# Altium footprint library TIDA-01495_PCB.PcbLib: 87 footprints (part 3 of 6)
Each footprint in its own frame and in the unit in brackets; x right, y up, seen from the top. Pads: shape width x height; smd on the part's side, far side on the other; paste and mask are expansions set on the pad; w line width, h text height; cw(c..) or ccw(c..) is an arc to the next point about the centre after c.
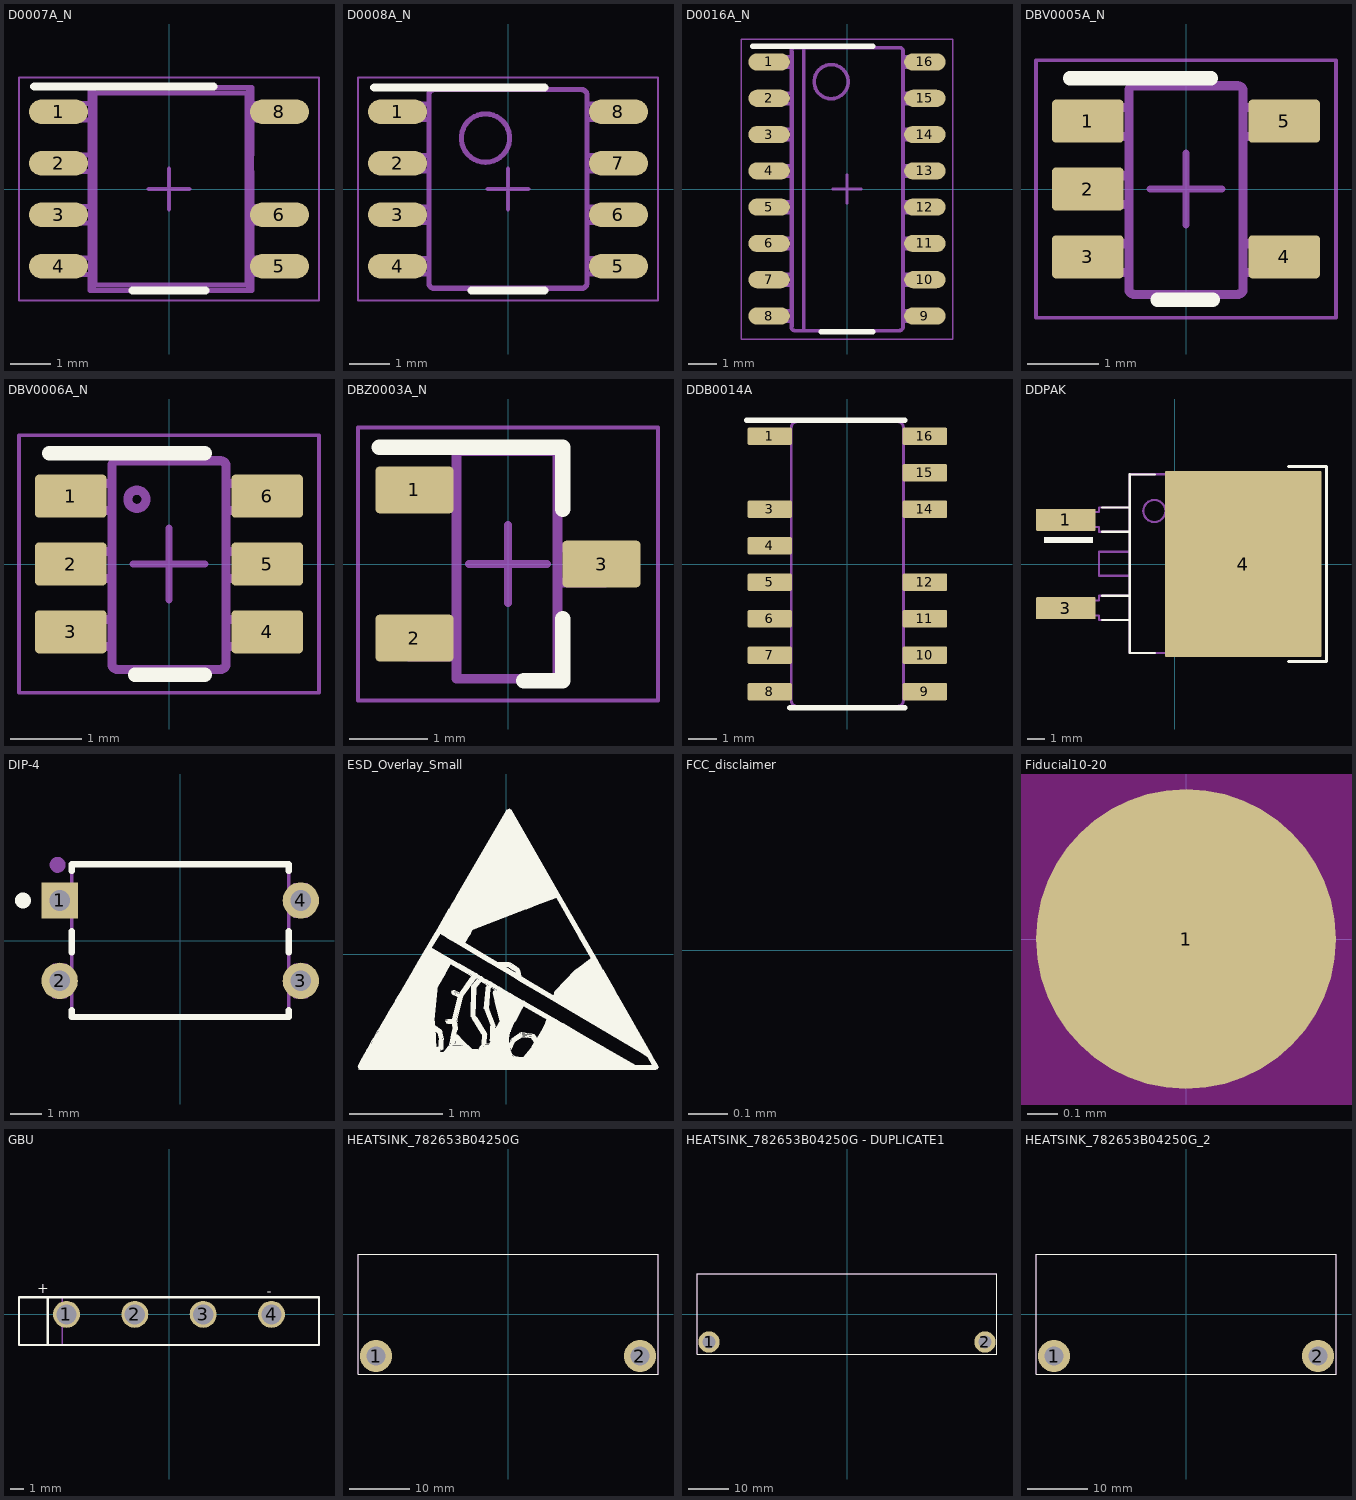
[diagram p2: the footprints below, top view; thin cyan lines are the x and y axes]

## D0007A_N [mm] "SOIC, 7-Leads, Body 4.9x3.9mm, Pitch 1.27mm, IPC Medium Density"
height 1.75
pads (7):
  oval 1.45x0.6 smd: 1(-2.725,1.905) 2(-2.725,0.635) 3(-2.725,-0.635) 4(-2.725,-1.905) 5(2.725,-1.905) 6(2.725,-0.635) 8(2.725,1.905)
Top Overlay:
  lines w0.2: -3.325,2.525 1.1,2.525 ; -0.9,-2.5 0.9,-2.5
Mechanical 5:
  lines w0.127: -1.95,-2.11 -1.95,-2.5 ; -1.95,-1.7 -1.95,-0.84 ; -1.95,-0.43 -1.95,0.43 ; -1.95,0.84 -1.95,1.7 ; -1.95,2.11 -1.95,2.5 ; 2.05,-2.11 2.05,-2.5 ; 2.05,-1.7 2.05,-0.84 ; 2.05,-0.43 2.05,0.43 2.03,0.43 2.03,0.84 2.05,0.84 2.05,1.7 ; 2.05,2.11 2.05,2.5 ; -2.325,-2.11 -2.325,-1.7 ; -2.325,-2.11 -2.045,-2.11 -1.931,-2.11 -1.931,-1.7 -2.045,-1.7 -2.325,-1.7 ; -2.325,-2.11 -2.39,-2.11 -2.95,-2.11 -2.95,-1.7 -2.39,-1.7 -2.325,-1.7 ; -2.325,-0.84 -2.325,-0.43 ; -2.325,-0.84 -2.045,-0.84 -1.931,-0.84 -1.931,-0.43 -2.045,-0.43 -2.325,-0.43 ; -2.325,-0.84 -2.39,-0.84 -2.95,-0.84 -2.95,-0.43 -2.39,-0.43 -2.325,-0.43 ; -2.325,0.43 -2.045,0.43 -1.931,0.43 -1.931,0.84 -2.045,0.84 -2.325,0.84 ; -2.325,0.43 -2.39,0.43 -2.95,0.43 -2.95,0.84 -2.39,0.84 -2.325,0.84 ; -2.325,0.43 -2.325,0.84 ; -2.325,1.7 -2.045,1.7 -1.931,1.7 -1.931,2.11 -2.045,2.11 -2.325,2.11 ; -2.325,1.7 -2.325,2.11 ; -2.325,1.7 -2.39,1.7 -2.95,1.7 -2.95,2.11 -2.39,2.11 -2.325,2.11 ; -1.95,-2.5 2.05,-2.5 ; -1.95,-2.5 -1.822,-2.372 ; -1.95,2.5 -1.822,2.372 ; -1.95,2.5 2.05,2.5 ; -1.822,-2.372 -1.822,2.372 ; -1.822,-2.372 1.922,-2.372 ; -1.822,2.372 1.922,2.372 ; 1.922,-2.372 1.922,2.372 ; 1.922,-2.372 2.05,-2.5 ; 1.922,2.372 2.05,2.5 ; 2.425,-2.11 2.49,-2.11 3.05,-2.11 3.05,-1.7 2.49,-1.7 2.425,-1.7 ; 2.425,-2.11 2.145,-2.11 2.031,-2.11 2.031,-1.7 2.145,-1.7 2.425,-1.7 ; 2.425,-2.11 2.425,-1.7 ; 2.425,-0.84 2.49,-0.84 3.05,-0.84 3.05,-0.43 2.49,-0.43 2.425,-0.43 ; 2.425,-0.84 2.145,-0.84 2.031,-0.84 2.031,-0.43 2.145,-0.43 2.425,-0.43 ; 2.425,-0.84 2.425,-0.43 ; 2.425,1.7 2.49,1.7 3.05,1.7 3.05,2.11 2.49,2.11 2.425,2.11 ; 2.425,1.7 2.145,1.7 2.031,1.7 2.031,2.11 2.145,2.11 2.425,2.11 ; 2.425,1.7 2.425,2.11
  text ".Designator" at -1.4,-0.4 h0.76
Mechanical 15:
  lines w0.05: -3.7,-2.75 3.7,-2.75 3.7,2.75 -3.7,2.75 -3.7,-2.75
  lines w0.1: -0.5,0 0.5,0 ; 0,-0.5 0,0.5
3D body "D0007A.stp": height 1.75, standoff 0, extent -3.01,-2.45 3.01,2.45

## D0008A_N [mm] "SOIC, 8-Leads, Body 4.9x3.9mm, Pitch 1.27mm, IPC Medium Density"
height 1.75
pads (8):
  oval 1.45x0.6 smd: 1(-2.725,1.905) 2(-2.725,0.635) 3(-2.725,-0.635) 4(-2.725,-1.905) 5(2.725,-1.905) 6(2.725,-0.635) 7(2.725,0.635) 8(2.725,1.905)
Top Overlay:
  lines w0.2: -3.3,2.5 0.9,2.5 ; -0.9,-2.5 0.9,-2.5
Mechanical 5:
  lines w0.127: -2.375,-2.095 -2.375,-1.715 ; -2.375,-2.095 -2.589,-2.095 -3.002,-2.095 -3.002,-1.715 -2.589,-1.715 -2.375,-1.715 ; -2.375,-2.095 -1.995,-2.095 -1.952,-2.095 -1.952,-1.715 -1.995,-1.715 -2.375,-1.715 ; -2.375,-0.825 -2.375,-0.445 ; -2.375,-0.825 -2.589,-0.825 -3.002,-0.825 -3.002,-0.445 -2.589,-0.445 -2.375,-0.445 ; -2.375,-0.825 -1.995,-0.825 -1.952,-0.825 -1.952,-0.445 -1.995,-0.445 -2.375,-0.445 ; -2.375,0.445 -2.375,0.825 ; -2.375,0.445 -2.589,0.445 -3.002,0.445 -3.002,0.825 -2.589,0.825 -2.375,0.825 ; -2.375,0.445 -1.995,0.445 -1.952,0.445 -1.952,0.825 -1.995,0.825 -2.375,0.825 ; -2.375,1.715 -2.375,2.095 ; -2.375,1.715 -2.589,1.715 -3.002,1.715 -3.002,2.095 -2.589,2.095 -2.375,2.095 ; -2.375,1.715 -1.995,1.715 -1.952,1.715 -1.952,2.095 -1.995,2.095 -2.375,2.095 ; -0.332,-2.45 -0.182,-2.45 ; -0.332,-2.45 -0.182,-2.45 ; -0.332,-2.45 -1.825,-2.45 -1.826,-2.45 cw(c-1.825,-2.323) -1.952,-2.324 -1.952,-2.323 -1.952,2.323 -1.952,2.324 cw(c-1.825,2.323) -1.826,2.45 -1.825,2.45 -0.332,2.45 ; -0.332,2.45 -0.182,2.45 ; -0.332,2.45 -0.182,2.45 ; -0.182,-2.45 0.178,-2.45 ; -0.182,2.45 0.178,2.45 ; 0.178,-2.45 0.328,-2.45 ; 0.178,-2.45 0.328,-2.45 ; 0.178,2.45 0.328,2.45 ; 0.178,2.45 0.328,2.45 ; 0.328,-2.45 1.821,-2.45 1.822,-2.45 ccw(c1.821,-2.323) 1.948,-2.324 1.948,-2.323 1.948,2.323 1.948,2.324 ccw(c1.821,2.323) 1.822,2.45 1.821,2.45 0.328,2.45 ; 2.371,-2.095 2.371,-1.715 ; 2.371,-2.095 1.991,-2.095 1.948,-2.095 1.948,-1.715 1.991,-1.715 2.371,-1.715 ; 2.371,-2.095 2.585,-2.095 2.998,-2.095 2.998,-1.715 2.585,-1.715 2.371,-1.715 ; 2.371,-0.825 2.371,-0.445 ; 2.371,-0.825 1.991,-0.825 1.948,-0.825 1.948,-0.445 1.991,-0.445 2.371,-0.445 ; 2.371,-0.825 2.585,-0.825 2.998,-0.825 2.998,-0.445 2.585,-0.445 2.371,-0.445 ; 2.371,0.445 2.371,0.825 ; 2.371,0.445 1.991,0.445 1.948,0.445 1.948,0.825 1.991,0.825 2.371,0.825 ; 2.371,0.445 2.585,0.445 2.998,0.445 2.998,0.825 2.585,0.825 2.371,0.825 ; 2.371,1.715 2.371,2.095 ; 2.371,1.715 1.991,1.715 1.948,1.715 1.948,2.095 1.991,2.095 2.371,2.095 ; 2.371,1.715 2.585,1.715 2.998,1.715 2.998,2.095 2.585,2.095 2.371,2.095 ; -0.555,0.659 ccw(c-0.555,1.256) -0.555,1.853 ccw(c-0.555,1.256) -0.555,0.659
  text ".Designator" at 0.411,-1.12 h0.89
Mechanical 15:
  lines w0.05: -3.7,-2.75 -3.7,2.75 3.7,2.75 3.7,-2.75 -3.7,-2.75
  lines w0.1: -0.5,0 0.5,0 ; 0,-0.5 0,0.5
3D body "D0008A.stp": height 1.63, standoff 0, extent -3,-2.45 3,2.45

## D0016A_N [mm] "SOIC, 16-Leads, Body 9.9x3.9mm, Pitch 1.27mm, IPC Medium Density"
height 1.75
pads (16):
  oval 1.45x0.6 smd: 1(-2.725,4.445) 2(-2.725,3.175) 3(-2.725,1.905) 4(-2.725,0.635) 5(-2.725,-0.635) 6(-2.725,-1.905) 7(-2.725,-3.175) 8(-2.725,-4.445) 9(2.725,-4.445) 10(2.725,-3.175) 11(2.725,-1.905) 12(2.725,-0.635) 13(2.725,0.635) 14(2.725,1.905) 15(2.725,3.175) 16(2.725,4.445)
Top Overlay:
  lines w0.2: -3.3,5 0.9,5 ; -0.9,-5 0.9,-5
Mechanical 5:
  drawing of 204 lines, arcs and shapes, not listed
  text ".Designator" at -1.2,-0.4 h0.76
Mechanical 15:
  lines w0.05: -3.7,-5.25 3.7,-5.25 3.7,5.25 -3.7,5.25 -3.7,-5.25
  lines w0.1: -0.5,0 0.5,0 ; 0,-0.5 0,0.5
3D body "D0016A.stp": height 1.6, standoff 0, extent -2.997,-4.953 2.997,4.953

## DBV0005A_N [mm] "SOT23, 5-Leads, Body 2.9x1.6mm, Pitch 0.95mm, Lead Span 2.8mm, IPC Medium Density"
height 1.45
pads (5):
  rrect17% 1x0.6 smd: 1(-1.375,0.95) 2(-1.375,0) 3(-1.375,-0.95) 4(1.375,-0.95) 5(1.375,0.95)
Top Overlay:
  lines w0.2: -1.625,1.55 0.35,1.55 ; -0.4,-1.55 0.375,-1.55
Mechanical 5:
  lines w0.127: -0.801,1.371 cw(c-0.725,1.37) -0.725,1.446 ; -0.801,1.37 -0.801,1.371 ; -0.801,1.37 -0.801,-1.399 -0.801,-1.4 ccw(c-0.725,-1.399) -0.725,-1.475 ; -0.725,-1.475 0.723,-1.475 0.724,-1.475 ccw(c0.723,-1.399) 0.799,-1.4 0.799,-1.399 0.799,1.37 ; -0.725,-1.475 -0.725,-1.475 ; -0.725,1.446 -0.725,1.446 ; -0.725,1.446 0.723,1.446 0.724,1.446 cw(c0.723,1.37) 0.799,1.371 ; 0.799,1.37 0.799,1.371 ; -1.423,-1.167 -1.423,-0.767 -1.199,-0.767 -1.105,-0.767 -1.088,-0.767 -0.835,-0.767 -0.801,-0.767 -0.801,-1.167 -0.835,-1.167 -1.088,-1.167 -1.105,-1.167 -1.199,-1.167 -1.423,-1.167 ; -1.423,-0.215 -1.423,0.186 -1.199,0.186 -1.105,0.186 -1.088,0.186 -0.835,0.186 -0.801,0.186 -0.801,-0.215 -0.835,-0.215 -1.088,-0.215 -1.105,-0.215 -1.199,-0.215 -1.423,-0.215 ; -1.423,0.738 -1.423,1.138 -1.199,1.138 -1.105,1.138 -1.088,1.138 -0.835,1.138 -0.801,1.138 -0.801,0.738 -0.835,0.738 -1.088,0.738 -1.105,0.738 -1.199,0.738 -1.423,0.738 ; 0.799,-1.167 0.834,-1.167 1.087,-1.167 1.103,-1.167 1.198,-1.167 1.422,-1.167 1.422,-0.767 1.198,-0.767 1.103,-0.767 1.087,-0.767 0.834,-0.767 0.799,-0.767 0.799,-1.167 ; 0.799,0.738 0.834,0.738 1.087,0.738 1.103,0.738 1.198,0.738 1.422,0.738 1.422,1.138 1.198,1.138 1.103,1.138 1.087,1.138 0.834,1.138 0.799,1.138 0.799,0.738
  text ".Designator" at 0.263,-0.693 h0.51
Mechanical 15:
  lines w0.05: -2.1,-1.8 -2.1,1.8 2.1,1.8 2.1,-1.8 -2.1,-1.8
  lines w0.1: -0.5,0 0.5,0 ; 0,-0.5 0,0.5
3D body "DBV0005A.stp": height 1.09, standoff 0, extent -1.422,-1.46 1.422,1.461

## DBV0006A_N [mm] "SOT23, 6-Leads, Body 2.9x1.6mm, Pitch 0.95mm, Lead Span 2.8mm, IPC Medium Density"
height 1.45
pads (6):
  rrect17% 1x0.6 smd: 1(-1.375,0.95) 2(-1.375,0) 3(-1.375,-0.95) 4(1.375,-0.95) 5(1.375,0) 6(1.375,0.95)
Top Overlay:
  lines w0.2: -1.675,1.55 0.5,1.55 ; -0.475,-1.55 0.5,-1.55
Mechanical 5:
  lines w0.127: 0.724,-1.475 ccw(c0.723,-1.399) 0.8,-1.399 0.8,1.37 ccw(c0.723,1.37) 0.724,1.446 ; 0.723,-1.475 0.724,-1.475 ; 0.723,-1.475 -0.724,-1.475 -0.725,-1.475 cw(c-0.724,-1.399) -0.801,-1.399 -0.801,1.37 cw(c-0.724,1.37) -0.725,1.446 -0.724,1.446 0.723,1.446 ; 0.723,1.446 0.724,1.446 ; -1.423,-1.154 -1.206,-1.154 -1.113,-1.154 -1.081,-1.154 -0.828,-1.154 -0.801,-1.154 -0.801,-0.78 -0.828,-0.78 -1.081,-0.78 -1.113,-0.78 -1.206,-0.78 -1.423,-0.78 -1.423,-1.154 ; -1.423,-0.202 -1.206,-0.202 -1.113,-0.202 -1.081,-0.202 -0.828,-0.202 -0.801,-0.202 -0.801,0.173 -0.828,0.173 -1.081,0.173 -1.113,0.173 -1.206,0.173 -1.423,0.173 -1.423,-0.202 ; -1.423,0.751 -1.206,0.751 -1.113,0.751 -1.081,0.751 -0.828,0.751 -0.801,0.751 -0.801,1.125 -0.828,1.125 -1.081,1.125 -1.113,1.125 -1.206,1.125 -1.423,1.125 -1.423,0.751 ; -0.577,0.906 cw(c-0.45,0.906) -0.323,0.906 cw(c-0.45,0.906) -0.577,0.906 ; 0.8,-1.154 0.827,-1.154 1.08,-1.154 1.112,-1.154 1.205,-1.154 1.422,-1.154 1.422,-0.78 1.205,-0.78 1.112,-0.78 1.08,-0.78 0.827,-0.78 0.8,-0.78 0.8,-1.154 ; 0.8,-0.202 0.827,-0.202 1.08,-0.202 1.112,-0.202 1.205,-0.202 1.422,-0.202 1.422,0.173 1.205,0.173 1.112,0.173 1.08,0.173 0.827,0.173 0.8,0.173 0.8,-0.202 ; 0.8,0.751 0.827,0.751 1.08,0.751 1.112,0.751 1.205,0.751 1.422,0.751 1.422,1.125 1.205,1.125 1.112,1.125 1.08,1.125 0.827,1.125 0.8,1.125 0.8,0.751
  text ".Designator" at -0.075,0.925 h0.51
Mechanical 15:
  lines w0.05: -2.1,-1.8 2.1,-1.8 2.1,1.8 -2.1,1.8 -2.1,-1.8
  lines w0.1: -0.5,0 0.5,0 ; 0,-0.5 0,0.5
3D body "DBV0006A.stp": height 1.12, standoff 0, extent -1.422,-1.461 1.423,1.46

## DBZ0003A_N [mm] "SOT23, 3-Leads, Body 2.9x1.3mm, Pitch 0.95mm, Lead Span 2.4mm, IPC Medium Density"
height 1.12
pads (3):
  rrect17% 1x0.6 smd: 1(-1.2,0.95) 2(-1.2,-0.95) 3(1.2,0)
Top Overlay:
  lines w0.2: -1.651,1.5 0.7,1.5 0.7,0.7 ; 0.2,-1.5 0.7,-1.5 0.7,-0.7
Mechanical 5:
  lines w0.127: -1.27,-1.187 -1.27,-0.743 -1.063,-0.743 -1.005,-0.743 -0.814,-0.743 -0.66,-0.743 -0.66,-1.187 -0.814,-1.187 -1.005,-1.187 -1.063,-1.187 -1.27,-1.187 ; -1.27,0.718 -1.27,1.162 -1.063,1.162 -1.005,1.162 -0.814,1.162 -0.66,1.162 -0.66,0.718 -0.814,0.718 -1.005,0.718 -1.063,0.718 -1.27,0.718 ; -0.66,-1.473 -0.66,1.448 0.635,1.448 0.635,-1.473 -0.66,-1.473 ; 0.635,-0.235 0.789,-0.235 0.98,-0.235 1.037,-0.235 1.245,-0.235 1.245,0.21 1.037,0.21 0.98,0.21 0.789,0.21 0.635,0.21 0.635,-0.235
  text ".Designator" at -0.254,0.889 h0.51
Mechanical 15:
  lines w0.05: -1.925,-1.75 1.925,-1.75 1.925,1.75 -1.925,1.75 -1.925,-1.75
  lines w0.1: -0.5,0 0.5,0 ; 0,-0.5 0,0.5
3D body "DBZ0003A.stp": height 0.98, standoff 0, extent -1.257,-1.46 1.257,1.461

## DDB0014A [mm] "SMD, 14-Leads, Body 3.9x9.9mm, Pitch 1.27mm"
height 1.75
pads (14):
  rrect17% 1.55x0.6 smd: 1(-2.7,4.445) 3(-2.7,1.905) 4(-2.7,0.635) 5(-2.7,-0.635) 6(-2.7,-1.905) 7(-2.7,-3.175) 8(-2.7,-4.445) 9(2.7,-4.445) 10(2.7,-3.175) 11(2.7,-1.905) 12(2.7,-0.635) 14(2.7,1.905) 15(2.7,3.175) 16(2.7,4.445)
Top Overlay:
  lines w0.2: -3.5,5 2,5 ; -2,-5 2,-5
Mechanical 5:
  drawing of 288 lines, arcs and shapes, not listed
  text ".Designator" at 0.398,-0.837 h0.89
3D body "DDB0014A.stp": height 1.75, standoff 0, extent -3.013,-4.95 3.013,4.95

## DDPAK [mil] "D2-PAK, 3-Pads, Body 9.7x10.4mm (max), TO-263AB, using Vishay Silionix recommended pad sizes"
height 190
pads (3):
  rrect8% 135x49.49 smd: 1(-246.06,100) 3(-246.06,-100)
  rrect1% 355x420 smd paste-181.1: 4(155.51,0)
Top Overlay:
  rectangle: -295.28,47.25 -185.04,61.03
  lines w5: -164.37,-126.77 -101.38,-126.77 ; -164.37,-72.05 -101.38,-72.05 ; -164.37,73.23 -101.38,73.23 ; -164.37,127.95 -101.38,127.95 ; -101.38,202.95 -101.38,202.56 ; -44.29,-201.77 -101.38,-201.77 -101.38,-201.38 ; -44.29,-201.38 -101.38,-201.38 ; -44.29,202.56 -101.38,202.56 ; -101.38,-201.38 -101.38,202.56
  lines w7: 258.09,-220.47 344,-220.47 344,220.47 258.09,220.47
Top Paste:
  rectangle: -17.72,147.44 30.28,206.26
  rectangle: 42.09,147.44 90.08,206.26
  rectangle: 101.89,147.44 149.88,206.26
  rectangle: 161.69,147.44 209.69,206.26
  rectangle: 221.5,147.44 269.49,206.26
  rectangle: 281.3,147.44 329.29,206.26
  rectangle: -17.72,76.81 30.28,135.63
  rectangle: 42.09,76.81 90.08,135.63
  rectangle: 101.89,76.81 149.88,135.63
  rectangle: 161.69,76.81 209.69,135.63
  rectangle: 221.5,76.81 269.49,135.63
  rectangle: 281.3,76.81 329.29,135.63
  rectangle: -17.72,6.18 30.28,65
  rectangle: 42.09,6.18 90.08,65
  rectangle: 101.89,6.18 149.88,65
  rectangle: 161.69,6.18 209.69,65
  rectangle: 221.5,6.18 269.49,65
  rectangle: 281.3,6.18 329.29,65
  rectangle: -17.72,-64.45 30.28,-5.63
  rectangle: 42.09,-64.45 90.08,-5.63
  rectangle: 101.89,-64.45 149.88,-5.63
  rectangle: 161.69,-64.45 209.69,-5.63
  rectangle: 221.5,-64.45 269.49,-5.63
  rectangle: 281.3,-64.45 329.29,-5.63
  rectangle: -17.72,-135.08 30.28,-76.26
  rectangle: 42.09,-135.08 90.08,-76.26
  rectangle: 101.89,-135.08 149.88,-76.26
  rectangle: 161.69,-135.08 209.69,-76.26
  rectangle: 221.5,-135.08 269.49,-76.26
  rectangle: 281.3,-135.08 329.29,-76.26
  rectangle: 281.3,-205.71 329.29,-146.89
  rectangle: 221.5,-205.71 269.49,-146.89
  rectangle: 161.69,-205.71 209.69,-146.89
  rectangle: 101.89,-205.71 149.88,-146.89
  rectangle: 42.09,-205.71 90.08,-146.89
  rectangle: -17.72,-205.71 30.28,-146.89
Mechanical 5:
  lines w5: -101.38,-126.77 -171.06,-126.77 -171.06,-116.34 -183.27,-116.34 -223.81,-116.34 ; -101.38,-72.05 -171.06,-72.05 -171.06,-82.48 -183.27,-82.48 -223.81,-82.48 ; -101.38,-26.77 -171.06,-26.77 -171.06,27.95 -101.38,27.95 ; -101.38,73.23 -171.06,73.23 -171.06,83.66 -183.27,83.66 -223.81,83.66 ; -101.38,127.95 -171.06,127.95 -171.06,117.52 -183.27,117.52 -223.81,117.52 ; 268.43,-201.38 306.93,-201.38 323.43,-156.89 323.43,158.07 306.93,202.56 268.43,202.56 ; -223.81,-116.34 -246.26,-116.34 -296.26,-116.34 -296.26,-82.48 -246.26,-82.48 -223.81,-82.48 ; -223.81,-116.34 -223.81,-82.48 ; -223.81,83.66 -223.81,117.52 ; -223.81,83.66 -246.26,83.66 -296.26,83.66 -296.26,117.52 -246.26,117.52 -223.81,117.52 ; -101.38,-201.38 239.17,-201.38 ; -101.38,-201.38 -101.38,202.56 ; -101.38,-201.38 -101.38,-201.77 268.43,-201.77 ; -101.38,202.56 -101.38,202.95 268.43,202.95 ; -101.38,202.56 239.17,202.56 ; 239.17,-201.38 239.17,202.56 ; 239.17,-201.38 268.43,-201.77 ; 239.17,202.56 268.43,202.95 ; 268.43,-201.77 268.43,202.95 ; -70.58,119.94 cw(c-45.58,119.94) -20.58,119.94 cw(c-45.58,119.94) -70.58,119.94
  text ".Designator" at 74.53,28.43 h40
3D body "TO-263AB.stp": height 180.31, standoff 0, extent -295.27,-202.36 324.41,202.36

## DIP-4 [mm] "DIP, 4-Leads, Body 6.86x4.83mm, Pitch 2.54mm"
height 5.59
pads (4):
  rect 1.15x1.15 hole 0.65: 1(-3.81,1.27)
  round 1.15 hole 0.65: 2(-3.81,-1.27) 3(3.81,-1.27) 4(3.81,1.27)
Top Overlay:
  circle w0.25: c-4.971,1.27 r0.125
  lines w0.2: -3.43,-2.2 -3.43,-2.415 3.43,-2.415 3.43,-2.2 ; -3.43,-0.375 -3.43,0.3 ; -3.43,2.2 -3.43,2.415 3.43,2.415 3.43,2.2 ; 3.43,-0.375 3.43,0.3
Mechanical 5:
  circle w0.25: c-3.875,2.395 r0.125
  lines w0.1: -4.01,-1.47 -3.61,-1.47 ; -4.01,-1.07 -3.61,-1.07 ; -4.01,1.07 -3.61,1.07 ; -4.01,1.47 -3.61,1.47 ; 3.61,-1.47 4.01,-1.47 ; 3.61,-1.07 4.01,-1.07 ; 3.61,1.07 4.01,1.07 ; 3.61,1.47 4.01,1.47 ; -4.01,-1.77 -3.61,-1.77 -3.61,-0.77 -4.01,-0.77 -4.01,-1.77 ; -4.01,0.77 -3.61,0.77 -3.61,1.77 -4.01,1.77 -4.01,0.77 ; -3.43,-2.415 3.43,-2.415 3.43,2.415 -3.43,2.415 -3.43,-2.415 ; 3.61,-1.77 4.01,-1.77 4.01,-0.77 3.61,-0.77 3.61,-1.77 ; 3.61,0.77 4.01,0.77 4.01,1.77 3.61,1.77 3.61,0.77
  text ".Designator" at 0.869,-0.939 h1.02
3D body: height 2, standoff 1.5, extent -4.01,1.07 -3.61,1.77
3D body: height 2, standoff 0, extent -4.01,0.77 -3.61,1.77
3D body: height 0, standoff -2.5, extent -4.01,1.07 -3.61,1.47
3D body: height 2, standoff 0, extent 3.62,0.77 4.02,1.77
3D body: height 2, standoff 1.5, extent 3.62,0.77 4.02,1.47
3D body: height 2, standoff 0, extent 3.62,-1.77 4.02,-0.77
3D body: height 2, standoff 1.5, extent 3.62,-1.77 4.02,-1.07
3D body: height 2, standoff 0, extent -4.02,-1.77 -3.62,-0.77
3D body: height 2, standoff 1.5, extent -4.02,-1.47 -3.62,-0.77
3D body: height 0, standoff -2.5, extent -4.01,-1.47 -3.61,-1.07
3D body: height 0, standoff -2.5, extent 3.61,-1.47 4.01,-1.07
3D body: height 0, standoff -2.5, extent 3.61,1.07 4.01,1.47
3D body: height 5.59, standoff 0.51, extent -3.43,-2.415 3.43,2.415
3D body: height 3, standoff 2, extent -4.01,0.77 -3.005,1.47
3D body: height 3, standoff 2, extent 3.015,0.77 4.02,1.47
3D body: height 3, standoff 2, extent 3.015,-1.47 4.02,-0.77
3D body: height 3, standoff 2, extent -4.02,-1.47 -3.015,-0.77

## ESD_Overlay_Small [mm]
Top Overlay:
  drawing of 901 lines, arcs and shapes, not listed

## FCC_disclaimer [mm]
Top Overlay:
  text "For evaluation only; not FCC approved for resale." at -15.928,-0.353 h0.76

## Fiducial10-20 [mm]
height 13
pads (1):
  round 1 smd mask+0.5: 1(0,0)
Top Layer keep-out:
  circle w1.178: c0,0 r0.5

## GBU [mm] "Comchip / Diodes Inc diode bridge"
height 21.55
pads (4):
  round 2 hole 1.5: 1(-7.62,0) 2(-2.54,0) 3(2.54,0) 4(7.62,0)
Top Overlay:
  lines w0.178: -9.025,-2.28 -9.025,1.28 ; -11.15,-2.28 -7.95,-2.28 11.15,-2.28 11.15,1.28 -7.95,1.28 -11.15,1.28 -11.15,-2.28
  text "~" at 2.108,0.918 h0.76
  text "~" at -2.997,0.918 h0.76
  text "-" at 7.275,1.358 h0.76
  text "+" at -9.783,1.57 h0.76
Mechanical 5:
  lines w0.1: -7.95,-2.28 11.15,-2.28 11.15,1.28 -7.95,1.28 ; -7.95,-2.28 -11.15,-2.28 -11.15,1.28 -7.95,1.28 ; -7.95,-2.28 -7.95,1.28
  text "~" at 2.165,-5.77 h1.52
  text "~" at -2.915,-5.77 h1.52
  text "-" at 7.305,-5.012 h1.52
  text "+" at -8.165,-5.004 h1.52
  text ".Designator" at -0.926,-0.796 h1.02
3D body "GBU.stp": height 21.55, standoff -15.25, extent -11.15,-2.28 11.15,1.28

## HEATSINK_782653B04250G [mm] "Aavid"
height 28.5
pads (2):
  round 5.334 hole 3.175: 1(-22,-7) 2(22,-7)
Top Overlay:
  lines w0.178: -25,-10 -25,10 25,10 25,-10 -25,-10
Mechanical 5:
  lines w0.178: -25,-10 25,-10 25,10 -25,10 -25,-10
  text ".Designator" at 10.628,3.8 h1.02
  text "COMPONENT SIDE" at 5.95,6.855 h1.02
3D body: height 13, standoff 5.5, extent -25.019,4.318 25.019,5.842
3D body: height 13, standoff 5.5, extent -25.019,-0.762 25.019,0.762
3D body: height 13, standoff 5.5, extent -25.019,-10.033 25.019,-8.791
3D body: height 7, standoff 5.5, extent -25.019,-10.033 25.019,10.033
3D body: height 13, standoff 5.5, extent -25.019,-5.712 25.019,-4.359
3D body: height 13, standoff 5.5, extent -25.019,8.255 25.019,10.033

## HEATSINK_782653B04250G - DUPLICATE1 [mm] "Aavid"
height 28.5
pads (2):
  round 5.334 hole 3.175: 1(-34.5,-7) 2(34.5,-7)
Top Overlay:
  lines w0.178: -37.5,-10 -37.5,10 37.5,10 37.5,-10 -37.5,-10
Mechanical 5:
  lines w0.178: -37.5,-10 37.5,-10 37.5,10 -37.5,10 -37.5,-10
  text ".Designator" at -23.687,-1.574 h1.02
  text "COMPONENT SIDE" at -28.556,1.195 h1.02
3D body: height 13, standoff 5.5, extent -37.465,4.318 37.5,5.842
3D body: height 13, standoff 5.5, extent -37.5,-0.762 37.5,0.762
3D body: height 13, standoff 5.5, extent -37.5,-10.033 37.5,-8.777
3D body: height 7, standoff 5.5, extent -37.5,-10.033 37.5,10.033
3D body: height 13, standoff 5.5, extent -37.465,-5.712 37.5,-4.345
3D body: height 13, standoff 5.5, extent -37.5,8.255 37.5,10.033

## HEATSINK_782653B04250G_2 [mm]
pads (2):
  round 5.334 hole 3.175: 1(-22,-7) 2(22,-7)
Top Overlay:
  lines w0.178: -25,-10 25,-10 25,10 -25,10 -25,-10
Mechanical 5:
  lines w0.178: -25,-10 -25,10 25,10 25,-10 -25,-10
  text "COMPONENT SIDE" at 23.595,7.617 h0.76
  text ".Designator" at 19.516,5.931 h1.02
3D body: height 13, standoff 5.5, extent -25.019,8.255 25.019,10.033
3D body: height 13, standoff 5.5, extent -25.019,-5.712 25.019,-4.359
3D body: height 7, standoff 5.5, extent -25.019,-10.033 25.019,10.033
3D body: height 13, standoff 5.5, extent -25.019,-10.033 25.019,-8.791
3D body: height 13, standoff 5.5, extent -25.019,-0.762 25.019,0.762
3D body: height 13, standoff 5.5, extent -25.019,4.318 25.019,5.842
